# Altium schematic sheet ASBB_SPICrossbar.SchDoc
size A4
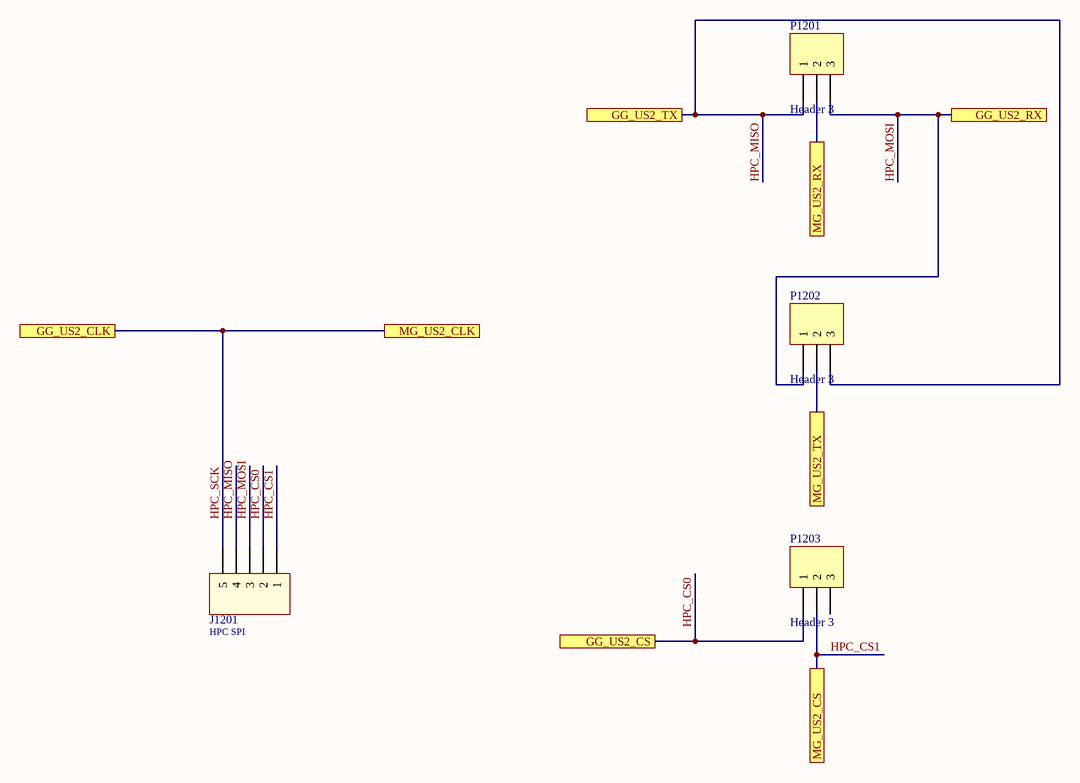
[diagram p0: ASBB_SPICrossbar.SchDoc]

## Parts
J1201  HPC SPI  [61000511921]
P1201  Header 3  [HDR1X3]
P1202  Header 3  [HDR1X3]
P1203  Header 3  [HDR1X3]

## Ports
GG_US2_CLK, GG_US2_CS, GG_US2_RX, GG_US2_TX, MG_US2_CLK, MG_US2_CS, MG_US2_RX, MG_US2_TX

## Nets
HPC_CS0: J1201.2 P1203.1 ; port GG_US2_CS
HPC_CS1: J1201.1 P1203.2 ; port MG_US2_CS
HPC_MISO: J1201.4 P1201.1 P1202.3 ; port GG_US2_TX
HPC_MOSI: J1201.3 P1201.3 P1202.1 ; port GG_US2_RX
HPC_SCK: J1201.5 ; port GG_US2_CLK, port MG_US2_CLK
MG_US2_RX: P1201.2 ; port MG_US2_RX
MG_US2_TX: P1202.2 ; port MG_US2_TX

Not connected (* = marked no-connect by the designer): P1203 3

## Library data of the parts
J1201 = 61000511921: Socket Header WR-PHD, Pitch 2.54 mm, SMT, Vertical, single row, 5 pin; Rated Current: 3 A; Pin Number: 5; Pitch: 2.54 mm; Working Voltage: 250 VAC; Contact Resistance: 20 mOhm; Insulation Resistance: >1000 MOhm
P1201-P1203 = Header 3: Header, 3-Pin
